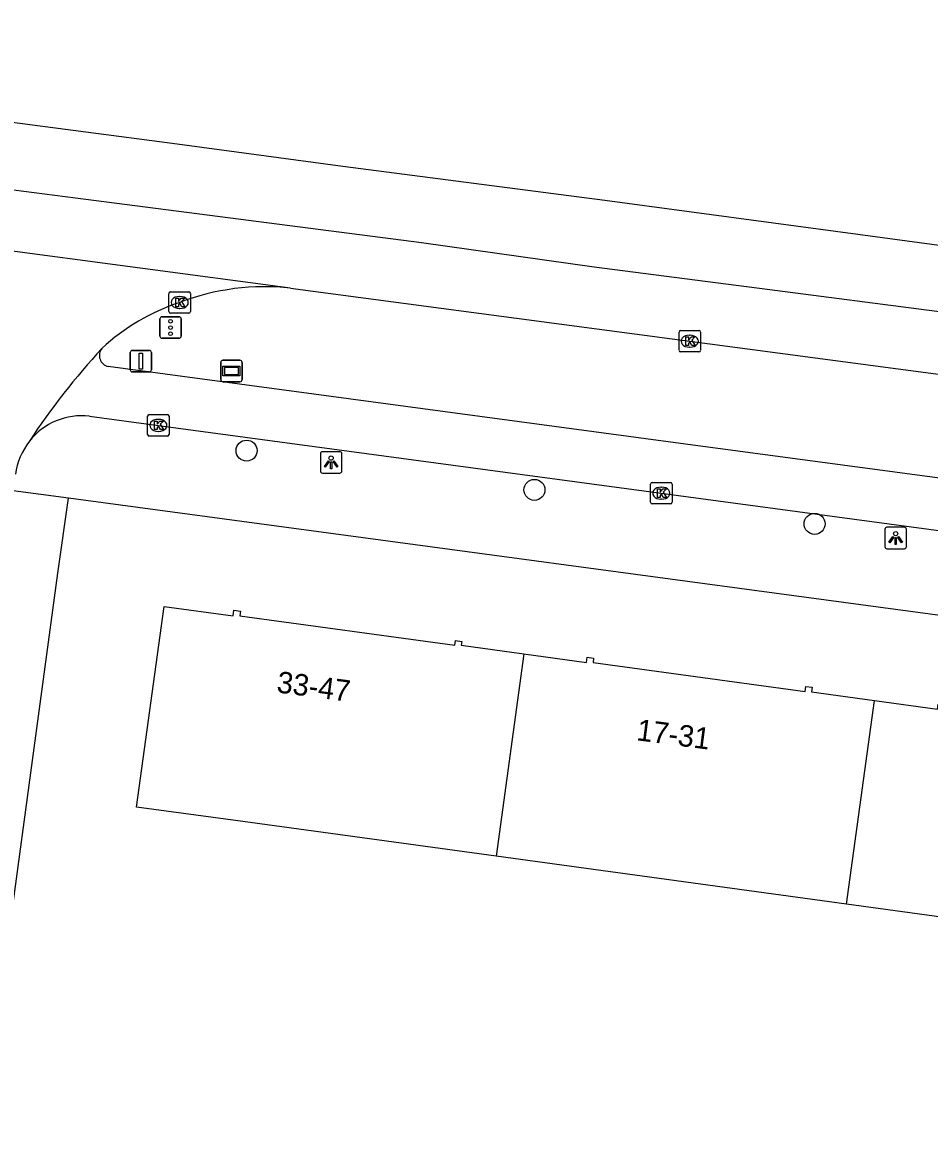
# Model space of a CAD drawing. Extents: x 161258 to 161838, y 380836 to 381727.
# Drawn here: x 161753.1 to 161795.3, y 381610.1 to 381662.4 of the extents above; entities that cross this region are included whole.
import ezdxf

# ---------------------------------------------------------------- set-up
doc = ezdxf.new("R2010")
doc.units = 0
for name, color, linetype in [('IMGEO_Boom', 7, 'Continuous'), ('IMGEO_Fietspad_open', 7, 'Continuous'), ('IMGEO_Kolk', 7, 'Continuous'), ('IMGEO_Lichtpunt', 7, 'Continuous'), ('IMGEO_Pand', 7, 'Continuous'), ('IMGEO_Pand_nummerreeks', 7, 'Continuous'), ('IMGEO_Rijbaan_lokaal_open', 7, 'Continuous'), ('IMGEO_Rijbaan_regionaal_gesloten', 7, 'Continuous'), ('IMGEO_Verkeersbordpaal', 7, 'Continuous'), ('IMGEO_Verkeersregelinstallatiepaal', 7, 'Continuous'), ('IMGEO_Verklikker', 7, 'Continuous'), ('IMGEO_Voetpad_open', 7, 'Continuous')]:
    doc.layers.add(name, color=color, linetype=linetype)

msp = doc.modelspace()

# ---------------------------------------------------------------- linework, layer by layer
at = {"layer": 'IMGEO_Boom'}
for centre in [(161763.534, 381642.423), (161776.941, 381640.597), (161789.989, 381639.013)]:
    msp.add_circle(centre, 0.489, dxfattribs=at)
at = {"layer": 'IMGEO_Fietspad_open'}
for points in [[(161817.064, 381638.3), (161814.773, 381638.602), (161805.681, 381639.828), (161783.977, 381642.719), (161757.086, 381646.342)], [(161756.215, 381644.03), (161759.426, 381643.601), (161782.848, 381640.443), (161812.273, 381636.483), (161821.453, 381635.279)]]:
    msp.add_lwpolyline(points, dxfattribs=at)
for centre, radius, start, end in [((161757.207, 381646.854), 0.526, 141.002, 256.7222), ((161755.859, 381640.953), 3.097, 83.4052, 141.9538)]:
    msp.add_arc(centre, radius, start, end, dxfattribs=at)
at = {"layer": 'IMGEO_Kolk'}
for p, q in [((161759.993, 381649.824), (161760.845, 381649.824)), ((161759.918, 381648.898), (161759.918, 381649.75)), ((161760.406, 381649.604), (161760.431, 381649.604)), ((161760.919, 381649.75), (161760.919, 381648.898)), ((161760.845, 381648.824), (161759.993, 381648.824)), ((161760.429, 381649.044), (161760.404, 381649.044)), ((161783.674, 381647.095), (161783.674, 381647.947)), ((161783.749, 381648.021), (161784.601, 381648.021)), ((161784.162, 381647.801), (161784.187, 381647.801)), ((161784.675, 381647.947), (161784.675, 381647.095)), ((161784.185, 381647.241), (161784.16, 381647.241)), ((161784.601, 381647.021), (161783.749, 381647.021)), ((161758.925, 381643.174), (161758.925, 381644.026)), ((161759, 381644.1), (161759.852, 381644.1)), ((161759.926, 381644.026), (161759.926, 381643.174)), ((161759.413, 381643.88), (161759.438, 381643.88)), ((161759.852, 381643.1), (161759, 381643.1)), ((161759.436, 381643.32), (161759.411, 381643.32)), ((161782.422, 381640.942), (161783.274, 381640.942)), ((161782.347, 381640.016), (161782.347, 381640.868)), ((161782.835, 381640.722), (161782.86, 381640.722)), ((161783.348, 381640.868), (161783.348, 381640.016)), ((161783.274, 381639.942), (161782.422, 381639.942)), ((161782.858, 381640.162), (161782.833, 381640.162))]:
    msp.add_line(p, q, dxfattribs=at)
for points in [[(161759.993, 381649.824), (161760.845, 381649.824)], [(161759.918, 381648.898), (161759.918, 381649.75)], [(161760.239, 381649.524), (161760.362, 381649.524), (161760.362, 381649.373), (161760.492, 381649.524), (161760.656, 381649.524), (161760.51, 381649.373), (161760.663, 381649.124), (161760.511, 381649.124), (161760.426, 381649.288), (161760.362, 381649.221), (161760.362, 381649.124), (161760.239, 381649.124), (161760.239, 381649.524)], [(161760.919, 381649.75), (161760.919, 381648.898)], [(161760.845, 381648.824), (161759.993, 381648.824)], [(161783.674, 381647.095), (161783.674, 381647.947)], [(161783.749, 381648.021), (161784.601, 381648.021)], [(161783.995, 381647.721), (161784.118, 381647.721), (161784.118, 381647.57), (161784.248, 381647.721), (161784.412, 381647.721), (161784.266, 381647.57), (161784.419, 381647.321), (161784.267, 381647.321), (161784.182, 381647.485), (161784.118, 381647.418), (161784.118, 381647.321), (161783.995, 381647.321), (161783.995, 381647.721)], [(161784.675, 381647.947), (161784.675, 381647.095)], [(161784.601, 381647.021), (161783.749, 381647.021)], [(161758.925, 381643.174), (161758.925, 381644.026)], [(161759, 381644.1), (161759.852, 381644.1)], [(161759.926, 381644.026), (161759.926, 381643.174)], [(161759.246, 381643.8), (161759.369, 381643.8), (161759.369, 381643.649), (161759.499, 381643.8), (161759.663, 381643.8), (161759.517, 381643.649), (161759.67, 381643.4), (161759.518, 381643.4), (161759.433, 381643.564), (161759.369, 381643.497), (161759.369, 381643.4), (161759.246, 381643.4), (161759.246, 381643.8)], [(161759.852, 381643.1), (161759, 381643.1)], [(161782.422, 381640.942), (161783.274, 381640.942)], [(161782.347, 381640.016), (161782.347, 381640.868)], [(161782.668, 381640.642), (161782.791, 381640.642), (161782.791, 381640.491), (161782.921, 381640.642), (161783.085, 381640.642), (161782.939, 381640.491), (161783.092, 381640.242), (161782.94, 381640.242), (161782.855, 381640.406), (161782.791, 381640.339), (161782.791, 381640.242), (161782.668, 381640.242), (161782.668, 381640.642)], [(161783.348, 381640.868), (161783.348, 381640.016)], [(161783.274, 381639.942), (161782.422, 381639.942)]]:
    msp.add_lwpolyline(points, dxfattribs=at)
for centre, start, end in [((161759.995, 381649.748), 91.552, 178.448), ((161759.995, 381649.748), 91.552, 178.448), ((161760.843, 381649.748), 1.552, 88.448), ((161760.843, 381649.748), 1.552, 88.448), ((161759.995, 381648.9), 181.552, 268.448), ((161759.995, 381648.9), 181.552, 268.448), ((161760.843, 381648.9), 271.552, 358.448), ((161760.843, 381648.9), 271.552, 358.448), ((161783.751, 381647.945), 91.552, 178.448), ((161783.751, 381647.945), 91.552, 178.448), ((161784.599, 381647.945), 1.552, 88.448), ((161784.599, 381647.945), 1.552, 88.448), ((161783.751, 381647.097), 181.552, 268.448), ((161783.751, 381647.097), 181.552, 268.448), ((161784.599, 381647.097), 271.552, 358.448), ((161784.599, 381647.097), 271.552, 358.448), ((161759.002, 381644.024), 91.552, 178.448), ((161759.002, 381644.024), 91.552, 178.448), ((161759.85, 381644.024), 1.552, 88.448), ((161759.85, 381644.024), 1.552, 88.448), ((161759.002, 381643.176), 181.552, 268.448), ((161759.002, 381643.176), 181.552, 268.448), ((161759.85, 381643.176), 271.552, 358.448), ((161759.85, 381643.176), 271.552, 358.448), ((161782.424, 381640.866), 91.552, 178.448), ((161782.424, 381640.866), 91.552, 178.448), ((161783.272, 381640.866), 1.552, 88.448), ((161783.272, 381640.866), 1.552, 88.448), ((161782.424, 381640.018), 181.552, 268.448), ((161782.424, 381640.018), 181.552, 268.448), ((161783.272, 381640.018), 271.552, 358.448), ((161783.272, 381640.018), 271.552, 358.448)]:
    msp.add_arc(centre, 0.0765, start, end, dxfattribs=at)
for centre, major_axis, ratio, start_param, end_param in [((161760.405, 381649.324), (-0.387, 0.002), 0.722429, 4.712389, 7.853982), ((161760.43, 381649.324), (-0.39, 0.002), 0.717154, 1.570796, 4.712389), ((161784.161, 381647.521), (-0.387, 0.002), 0.722429, 4.712389, 7.853982), ((161784.186, 381647.521), (-0.39, 0.002), 0.717154, 1.570796, 4.712389), ((161759.412, 381643.6), (-0.387, 0.002), 0.722429, 4.712389, 7.853982), ((161759.437, 381643.6), (-0.39, 0.002), 0.717154, 1.570796, 4.712389), ((161782.834, 381640.442), (-0.387, 0.002), 0.722429, 4.712389, 7.853982), ((161782.859, 381640.442), (-0.39, 0.002), 0.717154, 1.570796, 4.712389)]:
    msp.add_ellipse(centre, major_axis=major_axis, ratio=ratio, start_param=start_param, end_param=end_param, dxfattribs=at)
at = {"layer": 'IMGEO_Lichtpunt'}
for p, q in [((161766.974, 381642.278), (161766.974, 381641.471)), ((161766.974, 381642.278), (161766.974, 381641.471)), ((161767.876, 381642.373), (161767.068, 381642.373)), ((161767.876, 381642.373), (161767.068, 381642.373)), ((161767.97, 381641.471), (161767.97, 381642.278)), ((161767.97, 381641.471), (161767.97, 381642.278)), ((161767.068, 381641.377), (161767.876, 381641.377)), ((161767.068, 381641.377), (161767.876, 381641.377)), ((161794.168, 381638.852), (161793.36, 381638.852)), ((161794.168, 381638.852), (161793.36, 381638.852)), ((161793.266, 381638.757), (161793.266, 381637.95)), ((161793.266, 381638.757), (161793.266, 381637.95)), ((161794.262, 381637.95), (161794.262, 381638.757)), ((161794.262, 381637.95), (161794.262, 381638.757)), ((161793.36, 381637.856), (161794.168, 381637.856)), ((161793.36, 381637.856), (161794.168, 381637.856))]:
    msp.add_line(p, q, dxfattribs=at)
for points in [[(161767.348, 381641.942), (161767.387, 381641.914), (161767.199, 381641.652), (161767.161, 381641.679), (161767.348, 381641.942)], [(161767.56, 381641.914), (161767.598, 381641.941), (161767.785, 381641.679), (161767.746, 381641.651), (161767.56, 381641.914)], [(161767.45, 381641.894), (161767.497, 381641.894), (161767.497, 381641.572), (161767.45, 381641.572), (161767.45, 381641.894)], [(161793.64, 381638.421), (161793.679, 381638.393), (161793.491, 381638.131), (161793.453, 381638.158), (161793.64, 381638.421)], [(161793.742, 381638.373), (161793.789, 381638.373), (161793.789, 381638.051), (161793.742, 381638.051), (161793.742, 381638.373)], [(161793.852, 381638.393), (161793.89, 381638.42), (161794.077, 381638.158), (161794.038, 381638.13), (161793.852, 381638.393)]]:
    msp.add_lwpolyline(points, dxfattribs=at)
for centre in [(161767.473, 381642.076), (161793.765, 381638.555)]:
    msp.add_circle(centre, 0.0994, dxfattribs=at)
for centre, start, end in [((161767.068, 381642.278), 90, 180), ((161767.068, 381642.278), 90, 180), ((161767.876, 381642.278), 0, 90), ((161767.876, 381642.278), 0, 90), ((161767.068, 381641.471), 180, 270), ((161767.068, 381641.471), 180, 270), ((161767.876, 381641.471), 270, 0), ((161767.876, 381641.471), 270, 360), ((161793.36, 381638.757), 90, 180), ((161793.36, 381638.757), 90, 180), ((161794.168, 381638.757), 0, 90), ((161794.168, 381638.757), 0, 90), ((161793.36, 381637.95), 180, 270), ((161793.36, 381637.95), 180, 270), ((161794.168, 381637.95), 270, 0), ((161794.168, 381637.95), 270, 360)]:
    msp.add_arc(centre, 0.0946, start, end, dxfattribs=at)
at = {"layer": 'IMGEO_Pand'}
for points in [[(161775.161, 381623.531), (161763.365, 381625.144), (161758.411, 381625.822), (161759.689, 381635.165), (161762.912, 381634.724), (161762.948, 381634.987), (161763.244, 381634.947), (161763.215, 381634.732), (161773.232, 381633.362), (161773.261, 381633.575), (161773.553, 381633.535), (161773.53, 381633.362), (161776.451, 381632.962)], [(161776.451, 381632.962), (161775.161, 381623.531)], [(161776.451, 381632.962), (161779.372, 381632.562), (161779.404, 381632.799), (161779.699, 381632.759), (161779.671, 381632.55), (161789.542, 381631.2), (161789.574, 381631.438), (161789.869, 381631.398), (161789.84, 381631.188), (161792.775, 381630.786)], [(161791.477, 381621.299), (161792.775, 381630.786)], [(161792.775, 381630.786), (161795.709, 381630.385), (161795.739, 381630.612), (161796.034, 381630.572), (161796.003, 381630.342), (161805.958, 381629.018), (161805.989, 381629.251), (161806.285, 381629.211), (161806.253, 381628.967), (161809.318, 381628.548), (161808.945, 381625.742)], [(161791.477, 381621.299), (161775.161, 381623.531)], [(161808.179, 381620.968), (161807.917, 381619.051), (161791.477, 381621.299)]]:
    msp.add_lwpolyline(points, dxfattribs=at)
at = {"layer": 'IMGEO_Rijbaan_lokaal_open'}
for centre, radius, start, end in [((161764.389, 381638.94), 11.119, 83.8181, 110.9015), ((161763.501, 381639.981), 9.84, 108.2343, 132.9369), ((161781.839, 381624.137), 34.034, 137.3728, 146.619), ((161756.027, 381640.852), 3.292, 142.367, 171.7761)]:
    msp.add_arc(centre, radius, start, end, dxfattribs=at)
at = {"layer": 'IMGEO_Rijbaan_regionaal_gesloten'}
for points in [[(161817.985, 381645.977), (161809.404, 381647.011), (161803.595, 381647.872), (161795.685, 381648.9), (161787.775, 381649.927), (161779.72, 381650.974), (161771.676, 381652.109), (161763.62, 381653.148), (161755.563, 381654.187), (161747.855, 381655.181), (161741.235, 381656.106), (161737.26, 381656.662), (161731.03, 381657.39), (161727.522, 381657.865), (161719.602, 381658.939), (161715.452, 381659.519), (161711.437, 381660.002), (161707.421, 381660.485), (161703.427, 381661.121), (161699.432, 381661.756), (161695.592, 381662.368), (161694.46, 381661.561)], [(161752.017, 381657.797), (161760.062, 381656.742), (161768.015, 381655.67), (161780.225, 381654.094), (161791.997, 381652.507), (161804.072, 381650.88), (161812.54, 381649.8), (161816.526, 381649.239), (161818.365, 381648.98)], [(161765.586, 381649.994), (161751.562, 381651.859)], [(161765.586, 381649.994), (161813.403, 381643.636), (161817.619, 381643.088)]]:
    msp.add_lwpolyline(points, dxfattribs=at)
at = {"layer": 'IMGEO_Verkeersbordpaal'}
for p, q in [((161758.115, 381646.189), (161758.115, 381646.989)), ((161758.115, 381646.989), (161758.115, 381646.189)), ((161758.215, 381647.089), (161759.005, 381647.089)), ((161759.005, 381647.089), (161758.215, 381647.089)), ((161759.105, 381646.989), (161759.105, 381646.189)), ((161759.105, 381646.189), (161759.105, 381646.989)), ((161759.005, 381646.089), (161758.215, 381646.089)), ((161758.215, 381646.089), (161759.005, 381646.089))]:
    msp.add_line(p, q, dxfattribs=at)
msp.add_lwpolyline([(161758.535, 381646.964), (161758.685, 381646.964), (161758.685, 381646.214), (161758.535, 381646.214), (161758.535, 381646.964)], dxfattribs=at)
for centre, start, end in [((161758.215, 381646.989), 90, 180), ((161758.215, 381646.989), 90, 180), ((161759.005, 381646.989), 0, 90), ((161759.005, 381646.989), 360, 90), ((161758.215, 381646.189), 180, 270), ((161758.215, 381646.189), 180, 270), ((161759.005, 381646.189), 270, 0), ((161759.005, 381646.189), 270, 0)]:
    msp.add_arc(centre, 0.1, start, end, dxfattribs=at)
at = {"layer": 'IMGEO_Verkeersregelinstallatiepaal'}
for p, q in [((161759.501, 381647.758), (161759.501, 381648.558)), ((161759.501, 381648.558), (161759.501, 381647.758)), ((161759.601, 381648.658), (161760.391, 381648.658)), ((161760.391, 381648.658), (161759.601, 381648.658)), ((161760.491, 381648.558), (161760.491, 381647.758)), ((161760.491, 381647.758), (161760.491, 381648.558)), ((161760.391, 381647.658), (161759.601, 381647.658)), ((161759.601, 381647.658), (161760.391, 381647.658))]:
    msp.add_line(p, q, dxfattribs=at)
for centre in [(161759.996, 381648.448), (161759.996, 381648.158), (161759.996, 381647.868)]:
    msp.add_circle(centre, 0.085, dxfattribs=at)
for centre, start, end in [((161759.601, 381648.558), 90, 180), ((161759.601, 381648.558), 90, 180), ((161760.391, 381648.558), 0, 90), ((161760.391, 381648.558), 360, 90), ((161759.601, 381647.758), 180, 270), ((161759.601, 381647.758), 180, 270), ((161760.391, 381647.758), 270, 0), ((161760.391, 381647.758), 270, 0)]:
    msp.add_arc(centre, 0.1, start, end, dxfattribs=at)
at = {"layer": 'IMGEO_Verklikker'}
for p, q in [((161762.434, 381646.632), (161763.224, 381646.632)), ((161763.224, 381646.632), (161762.434, 381646.632)), ((161762.334, 381645.732), (161762.334, 381646.532)), ((161762.334, 381646.532), (161762.334, 381645.732)), ((161763.324, 381646.532), (161763.324, 381645.732)), ((161763.324, 381645.732), (161763.324, 381646.532)), ((161763.224, 381645.632), (161762.434, 381645.632)), ((161762.434, 381645.632), (161763.224, 381645.632))]:
    msp.add_line(p, q, dxfattribs=at)
for points in [[(161762.435, 381646.364), (161763.223, 381646.364), (161763.223, 381645.9), (161762.435, 381645.9), (161762.435, 381646.364)], [(161762.5, 381646.299), (161762.5, 381645.965), (161763.158, 381645.965), (161763.158, 381646.299), (161762.5, 381646.299)]]:
    msp.add_lwpolyline(points, dxfattribs=at)
for centre, start, end in [((161762.434, 381646.532), 90, 180), ((161762.434, 381646.532), 90, 180), ((161763.224, 381646.532), 0, 90), ((161763.224, 381646.532), 360, 90), ((161762.434, 381645.732), 180, 270), ((161762.434, 381645.732), 180, 270), ((161763.224, 381645.732), 270, 0), ((161763.224, 381645.732), 270, 0)]:
    msp.add_arc(centre, 0.1, start, end, dxfattribs=at)
at = {"layer": 'IMGEO_Voetpad_open'}
for points in [[(161755.234, 381640.215), (161752.667, 381640.554)], [(161749.372, 381596.944), (161750.063, 381602.151), (161754.739, 381636.721), (161755.234, 381640.215)], [(161823.38, 381630.949), (161812.33, 381632.493), (161809.891, 381632.818), (161800.213, 381634.153), (161755.234, 381640.215)]]:
    msp.add_lwpolyline(points, dxfattribs=at)

# ---------------------------------------------------------------- texts
at = {"layer": 'IMGEO_Pand_nummerreeks'}
for s, rotation, p in [('33-47', 352.5216, (161764.903, 381631.166)), ('17-31', 352.6092, (161781.661, 381628.936))]:
    msp.add_text(s, height=1, rotation=rotation, dxfattribs=at).set_placement(p)

doc.saveas('drawing.dxf')
